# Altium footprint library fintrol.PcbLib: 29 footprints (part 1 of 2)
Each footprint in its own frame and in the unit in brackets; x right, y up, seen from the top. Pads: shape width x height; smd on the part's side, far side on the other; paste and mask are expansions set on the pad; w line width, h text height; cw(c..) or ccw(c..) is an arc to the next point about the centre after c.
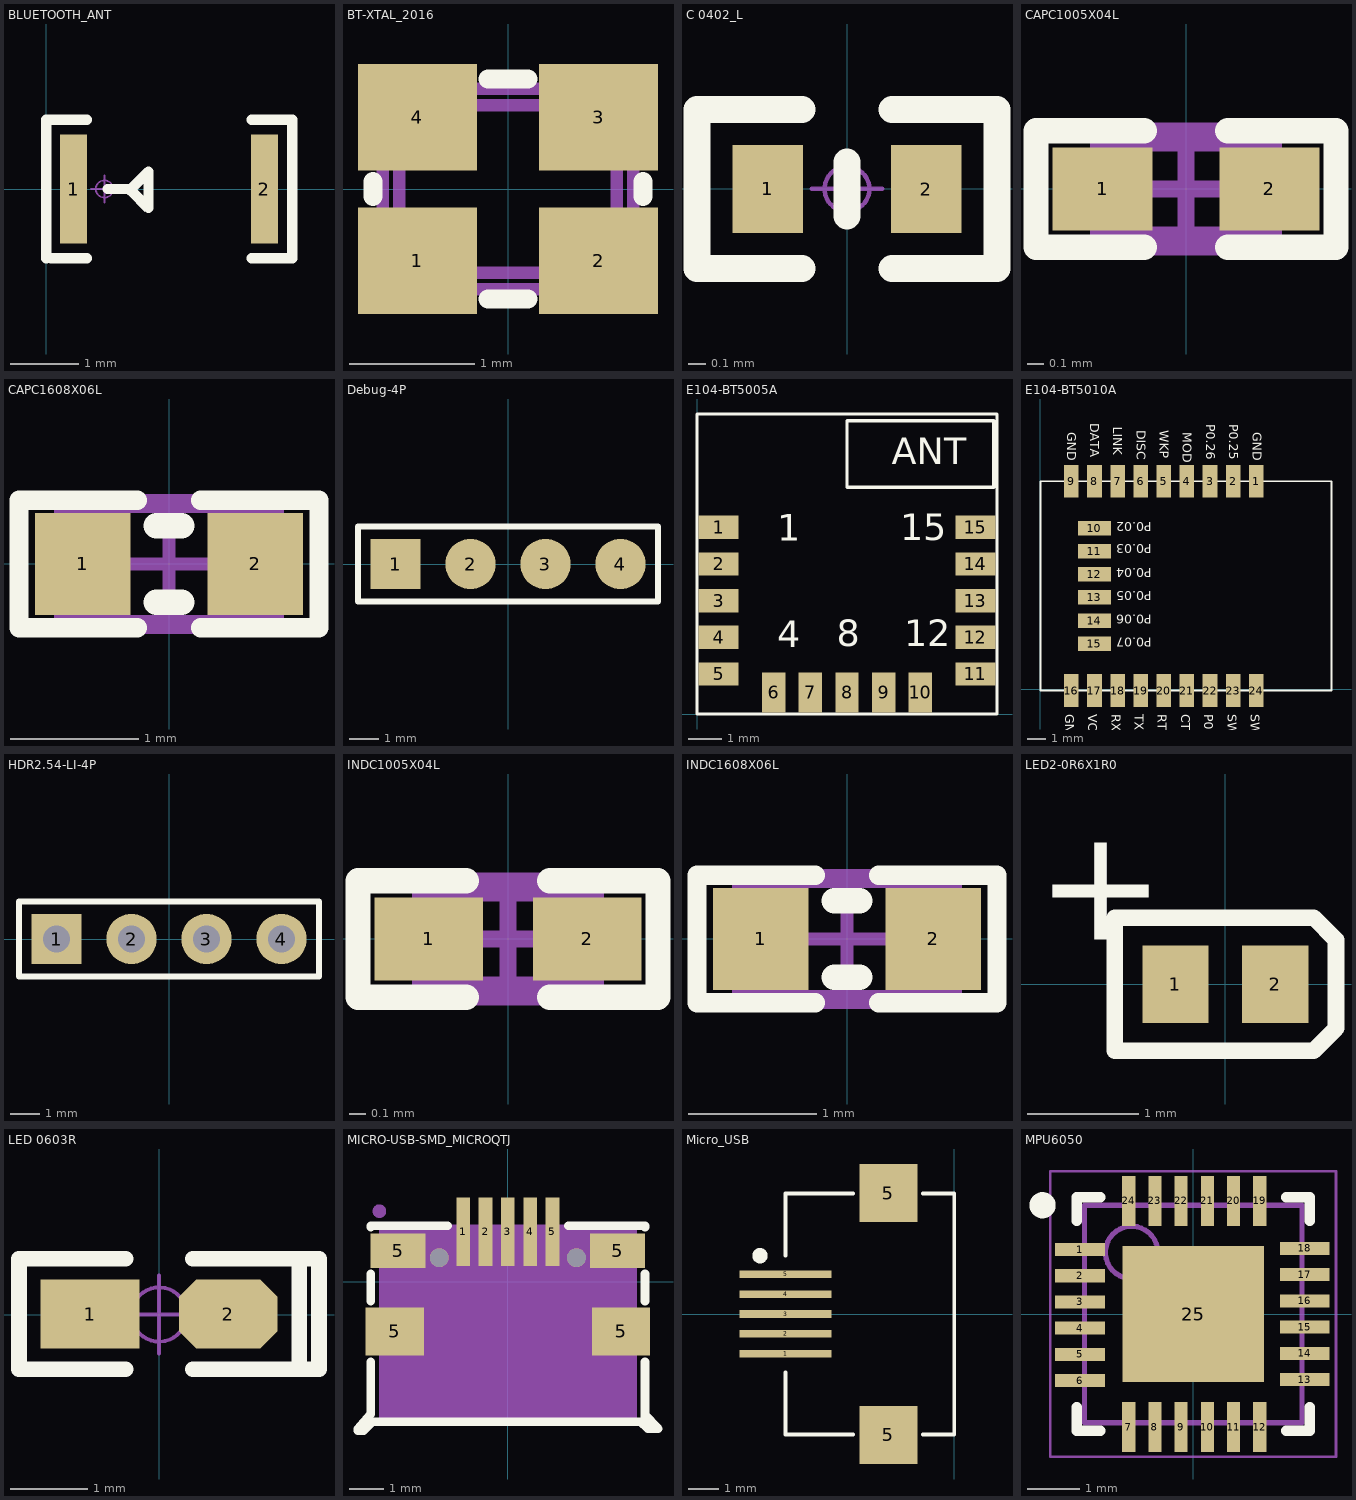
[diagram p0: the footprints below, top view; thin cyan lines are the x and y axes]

## BLUETOOTH_ANT [mm] "陶瓷表贴蓝牙天线"
pads (2):
  rect 0.4x1.6 smd: 1(0.4,0) 2(3.2,0)
Top Overlay:
  lines w0.152: 0,-1.016 0,-0.889 0,-0.62 0,1.016 0.596,1.016 ; 0.071,-1.016 0.596,-1.016 ; 0.901,0 1.228,0 1.228,-0.017 1.499,0.254 1.499,-0.279 1.245,-0.025 ; 3.011,-1.016 3.607,-1.016 3.607,1.016 3.011,1.016
Mechanical 15:
  circle w0.025: c0.853,0 r0.127
  lines w0.025: 0.653,0 1.052,0 ; 0.853,-0.2 0.853,0.2

## BT-XTAL_2016 [mm]
pads (4):
  rect 0.95x0.85 smd: 1(-0.725,-0.575) 2(0.725,-0.575) 3(0.725,0.575) 4(-0.725,0.575)
Top Overlay:
  lines w0.152: -1.08,-0.06 -1.08,0.06 ; -0.16,-0.88 0.16,-0.88 ; -0.16,0.88 0.16,0.88 ; 1.08,-0.06 1.08,0.06
Mechanical 7:
  lines w0.1: -1,-0.7 cw(c-1,-0.8) -0.9,-0.8 0.9,-0.8 cw(c1,-0.8) 1,-0.7 1,0.7 cw(c1,0.8) 0.9,0.8 -0.9,0.8 cw(c-1,0.8) -1,0.7 -1,-0.7 ; -0.87,-0.57 ccw(c-0.77,-0.57) -0.77,-0.67 0.77,-0.67 ccw(c0.77,-0.57) 0.87,-0.57 0.87,0.57 ccw(c0.77,0.57) 0.77,0.67 -0.77,0.67 ccw(c-0.77,0.57) -0.87,0.57 -0.87,-0.57
  text ".Designator" at -0.7,-0.2 h0.38
3D body "User Library-GeyerElectronics_KX5.step": height 0.56, standoff 0, extent -1.05,-0.85 1.05,0.85
3D body: height 0.56, standoff 0.15, extent -0.7,-0.65 0.7,0.65

## C 0402_L [mm] "无极性贴片电容"
pads (2):
  rect 0.4x0.5 smd: 1(-0.45,0) 2(0.45,0)
Top Overlay:
  lines w0.152: -0.254,-0.45 -0.85,-0.45 ; -0.254,0.45 -0.85,0.45 -0.85,-0.45 ; 0,-0.152 0,0.152 ; 0.254,-0.45 0.85,-0.45 0.85,0.45 0.254,0.45 ; -0.85,-0.45 -0.85,-0.45
Mechanical 15:
  circle w0.025: c0,0 r0.127
  lines w0.025: -0.2,0 0.2,0 ; 0,-0.2 0,0.2
3D body "C 0402.STEP": height 0.53, standoff 0.01, extent -0.5,-0.26 0.5,0.26

## CAPC1005X04L [mm]
pads (2):
  rect 0.6x0.5 smd: 1(-0.5,0) 2(0.5,0)
Top Overlay:
  lines w0.152: -0.25,-0.35 -0.9,-0.35 -0.9,0.35 -0.25,0.35 ; 0.25,-0.35 0.9,-0.35 0.9,0.35 0.25,0.35
Mechanical 7:
  lines w0.1: -0.525,-0.275 -0.525,0.275 0.525,0.275 0.525,-0.275 -0.525,-0.275
  text ".Designator" at -0.432,-0.152 h0.3
Mechanical 15:
  lines w0.1: -0.275,0 0.275,0 ; 0,-0.275 0,0.275 ; -0.9,-0.35 0.9,-0.35 0.9,0.35 -0.9,0.35 -0.9,-0.35
3D body "User Library-0402(1005M) Cap.step": height 0.5, standoff -0.01, extent -0.508,-0.254 0.508,0.254

## CAPC1608X06L [mm]
pads (2):
  rect 0.75x0.8 smd: 1(-0.675,0) 2(0.675,0)
Top Overlay:
  lines w0.152: -0.25,-0.5 -1.175,-0.5 -1.175,0.5 -0.25,0.5 ; 0.25,-0.5 1.175,-0.5 1.175,0.5 0.25,0.5
  lines w0.2: -0.1,-0.3 0.1,-0.3 ; -0.1,0.3 0.1,0.3
Mechanical 7:
  lines w0.1: -0.85,-0.45 0.85,-0.45 0.85,0.45 -0.85,0.45 -0.85,-0.45
  text ".Designator" at -0.685,-0.142 h0.38
Mechanical 15:
  lines w0.1: -0.45,0 0.45,0 ; 0,-0.45 0,0.45 ; -1.175,-0.5 -1.175,0.5 1.175,0.5 1.175,-0.5 -1.175,-0.5
3D body "User Library-Chip Capacitor 0603.step": height 0.8, standoff 0, extent -0.8,-0.43 0.8,0.43

## Debug-4P [mm]
pads (4):
  rect 1.7x1.7 smd: 1(-3.81,0)
  round 1.7 smd: 2(-1.27,0) 3(1.27,0) 4(3.81,0)
Top Overlay:
  lines w0.2: -5.08,-1.27 -5.08,1.27 5.08,1.27 5.08,-1.27 -5.08,-1.27

## E104-BT5005A [mm]
pads (15):
  rect 1.2x0.7 smd: 1(0.65,5.6) 2(0.65,4.5) 3(0.65,3.4) 4(0.65,2.3) 5(0.65,1.2) 11(8.35,1.2) 12(8.35,2.3) 13(8.35,3.4) 14(8.35,4.5) 15(8.35,5.6)
  rect 0.7x1.2 smd: 6(2.3,0.65) 7(3.4,0.65) 8(4.5,0.65) 9(5.6,0.65) 10(6.7,0.65)
Top Overlay:
  lines w0.1: 0,0 0,0.5 0,9 9,9 9,0 8.5,0 0,0 ; 4.5,6.8 8.9,6.8 8.9,8.8 4.5,8.8 4.5,6.8
  text "ANT" at 5.842,7.493 h0.8
  text "15" at 6.096,5.207 h0.8
  text "12" at 6.223,2.032 h0.8
  text "8" at 4.191,2.032 h0.8
  text "4" at 2.4,2 h0.8
  text "1" at 2.4,5.2 h0.8

## E104-BT5010A [mm]
pads (24):
  rect 0.8x1.8 smd: 1(11.86,11.43) 2(10.59,11.43) 3(9.32,11.43) 4(8.05,11.43) 5(6.78,11.43) 6(5.51,11.43) 7(4.24,11.43) 8(2.97,11.43) 9(1.7,11.43) 16(1.7,-0.07) 17(2.97,-0.07) 18(4.24,-0.07) 19(5.51,-0.07) 20(6.78,-0.07) 21(8.05,-0.07) 22(9.32,-0.07) 23(10.59,-0.07) 24(11.86,-0.07)
  rect 1.8x0.8 smd: 10(2.97,8.855) 11(2.97,7.585) 12(2.97,6.315) 13(2.97,5.045) 14(2.97,3.775) 15(2.97,2.505)
Top Overlay:
  lines w0.1: 0,-0.07 0,11.43 16,11.43 16,-0.07 0,-0.07
  text "GND" at 1.36,-1.361 h0.5
  text "GND" at 1.46,14.139 h0.5
  text "P0.03" at 6.123,7.976 h0.5
  text "P0.06" at 6.123,4.105 h0.5
  text "P0.02" at 6.123,9.174 h0.5
  text "P0.04" at 6.123,6.645 h0.5
  text "P0.05" at 6.123,5.375 h0.5
  text "P0.07" at 6.123,2.835 h0.5
  text "SWDIO" at 11.56,-1.361 h0.5
  text "SWDCLK" at 10.285,-1.361 h0.5
  text "P0.21/RST" at 9.01,-1.361 h0.5
  text "CTS" at 7.735,-1.361 h0.5
  text "RTS" at 6.46,-1.361 h0.5
  text "TXD" at 5.185,-1.361 h0.5
  text "RXD" at 3.91,-1.361 h0.5
  text "VCC" at 2.635,-1.361 h0.5
  text "DATA" at 2.735,14.63 h0.5
  text "LINK" at 4.01,14.427 h0.5
  text "DISC" at 5.285,14.236 h0.5
  text "WKP" at 6.56,14.242 h0.5
  text "MOD" at 7.835,14.139 h0.5
  text "P0.26" at 9.11,14.567 h0.5
  text "P0.25" at 10.385,14.567 h0.5
  text "GND" at 11.66,14.139 h0.5

## HDR2.54-LI-4P [mm] "排针，4脚"
pads (4):
  rect 1.7x1.7 hole 0.9: 1(-3.81,0)
  round 1.7 hole 0.9: 2(-1.27,0) 3(1.27,0) 4(3.81,0)
Top Overlay:
  lines w0.2: -5.08,-1.27 -5.08,1.27 5.08,1.27 5.08,-1.27 -5.08,-1.27
3D body "HDR2.54-1P.STEP": height 8.5, standoff -3, extent -5.08,-1.27 -2.54,1.27
3D body "HDR2.54-1P.STEP": height 8.5, standoff -3, extent -2.54,-1.27 0,1.27
3D body "HDR2.54-1P.STEP": height 8.5, standoff -3, extent 0,-1.27 2.54,1.27
3D body "HDR2.54-1P.STEP": height 8.5, standoff -3, extent 2.54,-1.27 5.08,1.27

## INDC1005X04L [mm]
pads (2):
  rect 0.65x0.5 smd: 1(-0.475,0) 2(0.475,0)
Top Overlay:
  lines w0.152: -0.25,-0.35 -0.9,-0.35 -0.9,0.35 -0.25,0.35 ; 0.25,-0.35 0.9,-0.35 0.9,0.35 0.25,0.35
Mechanical 7:
  lines w0.1: -0.525,-0.275 0.525,-0.275 0.525,0.275 -0.525,0.275 -0.525,-0.275
  text ".Designator" at -0.432,-0.152 h0.3
Mechanical 15:
  lines w0.1: -0.275,0 0.275,0 ; 0,-0.275 0,0.275 ; -0.9,-0.35 0.9,-0.35 0.9,0.35 -0.9,0.35 -0.9,-0.35
3D body "User Library-Chip Inductor 0402.step": height 0.5, standoff 0, extent -0.5,-0.3 0.5,0.3

## INDC1608X06L [mm]
pads (2):
  rect 0.75x0.8 smd: 1(-0.675,0) 2(0.675,0)
Top Overlay:
  lines w0.152: -0.25,-0.5 -1.175,-0.5 -1.175,0.5 -0.25,0.5 ; 0.25,-0.5 1.175,-0.5 1.175,0.5 0.25,0.5
  lines w0.2: -0.1,-0.3 0.1,-0.3 ; -0.1,0.3 0.1,0.3
Mechanical 7:
  lines w0.1: -0.85,-0.45 0.85,-0.45 0.85,0.45 -0.85,0.45 -0.85,-0.45
  text ".Designator" at -0.7,-0.2 h0.38
Mechanical 15:
  lines w0.1: -0.45,0 0.45,0 ; 0,-0.45 0,0.45 ; -1.175,-0.5 -1.175,0.5 1.175,0.5 1.175,-0.5 -1.175,-0.5
3D body "User Library-Chip Inductor.step": height 0.8, standoff 0, extent -0.8,-0.475 0.8,0.475

## LED2-0R6X1R0 [mm]
pads (2):
  rect 0.6x0.7 smd: 1(-0.45,0) 2(0.45,0)
Top Overlay:
  lines w0.15: -1,-0.6 -1,0.6 0.8,0.6 1,0.4 1,-0.4 0.8,-0.6 -1,-0.6
  text "+" at -1.71,0.4 h1.02

## LED 0603R [mil] "红色0603LED"
pads (2):
  rect 50x35 smd: 1(-35,0.26)
  oct 50x35 smd: 2(35,0.26)
Top Overlay:
  lines w8: -17,-27.74 -71,-27.74 -71,-25.74 -71,28.26 -70,28.26 -17,28.26 ; 17,-27.74 70,-27.74 ; 17,28.26 71,28.26 81,28.26 81,-27.74 71,-27.74 71,26.26
Mechanical 15:
  circle w1.97: c0,0 r13.78
  lines w1.97: -19.68,0 19.68,0 ; 0,-19.68 0,19.68
3D body "LED 0603玻璃罩.": height 0, standoff 0, extent 0,0 0,0
3D body "LED 0603-R.STEP": height 18.36, standoff -0.16, extent -31.5,-15.79 31.5,15.79

## MICRO-USB-SMD_MICROQTJ [mm]
pads (11):
  rect 0.4x2 smd: 1(-1.3,1.452) 2(-0.65,1.452) 3(0,1.452) 4(0.65,1.452) 5(1.3,1.452)
  rect 1.7x1.4 smd: 5(-3.3,-1.452) 5(3.3,-1.452)
  rect 1.6x1 smd: 5(-3.2,0.902) 5(3.2,0.902)
  round 0.55 hole 0.55 unplated: ""(-2,0.698) ""(2,0.698)
Top Overlay:
  lines w0.254: -4.011,-3.869 -4.369,-4.288 -4.369,-4.339 -4.204,-4.339 -3.946,-4.081 3.878,-4.081 4.084,-4.288 4.376,-4.288 3.99,-3.869 ; -4,-3.869 -4,-2.398 -4,-2.334 ; -4,-0.571 -4,0.22 ; -4,1.583 -4,1.633 -1.758,1.633 ; 1.758,1.633 4,1.633 4,1.583 ; 4,-3.991 4,-2.398 4,-2.334 ; 4,-0.571 4,0.22
Mechanical 4:
  circle w0.275: c2,0.698 r0.137
  circle w0.275: c-2,0.698 r0.137
  region: 3.754,-4.143 -3.746,-4.143 -3.746,1.657 3.754,1.657
Mechanical 5:
  region: 1.175,0.952 1.175,2.052 1.425,2.052 1.425,0.952
  region: 0.525,0.952 0.525,2.052 0.775,2.052 0.775,0.952
  region: -0.125,0.952 -0.125,2.052 0.125,2.052 0.125,0.952
  region: -0.775,0.952 -0.775,2.052 -0.525,2.052 -0.525,0.952
  region: -1.425,0.952 -1.425,2.052 -1.175,2.052 -1.175,0.952
  region: 2.525,-0.902 4.075,-0.902 4.075,-2.002 2.525,-2.002
  region: -4.075,-0.902 -2.525,-0.902 -2.525,-2.002 -4.075,-2.002
  region: 2.55,1.252 3.85,1.252 3.85,0.552 2.55,0.552
  region: -3.85,1.252 -2.55,1.252 -2.55,0.552 -3.85,0.552
Mechanical 6:
  circle w0.2: c-3.746,2.053 r0.1

## Micro_USB [mm] "5P 贴片 带定位柱"
pads (7):
  rect 3x0.25 smd: 1(-5.508,-1.3) 2(-5.508,-0.65) 3(-5.508,0) 4(-5.508,0.65) 5(-5.508,1.3)
  rect 1.9x1.9 smd: 5(-2.15,-3.95) 5(-2.15,3.95)
Top Overlay:
  circle w0.25: c-6.348,1.905 r0.125
  lines w0.127: -5.508,-3.937 -3.302,-3.937 ; -5.508,-3.9 -5.508,-1.905 ; -5.508,1.905 -5.508,3.9 ; -5.508,3.937 -3.302,3.937 ; -1.016,-3.937 0,-3.937 ; -1.016,3.937 0,3.937 ; 0,-3.9 0,3.9

## MPU6050 [mm] "QFN, 24-Leads, Body 4.00x4.00mm, Pitch 0.50mm, Thermal Pad 2.70x2.60mm, IPC Medium Density"
height 0.9
pads (25):
  rect 0.95x0.25 smd: 1(-2.159,1.23) 2(-2.159,0.73) 3(-2.159,0.23) 4(-2.159,-0.27) 5(-2.159,-0.77) 6(-2.159,-1.27) 13(2.127,-1.25) 14(2.127,-0.75) 15(2.127,-0.25) 16(2.127,0.25) 17(2.127,0.75) 18(2.127,1.25)
  rect 0.25x0.95 smd: 7(-1.23,-2.159) 8(-0.73,-2.159) 9(-0.23,-2.159) 10(0.27,-2.159) 11(0.77,-2.159) 12(1.27,-2.159) 19(1.27,2.159) 20(0.77,2.159) 21(0.27,2.159) 22(-0.23,2.159) 23(-0.73,2.159) 24(-1.23,2.159)
  rect 2.7x2.6 smd: 25(0,0)
Top Overlay:
  circle w0.25: c-2.875,2.075 r0.125
  lines w0.2: -2.225,-1.775 -2.225,-2.225 -1.775,-2.225 ; -2.225,1.775 -2.225,2.225 -1.775,2.225 ; 1.775,-2.225 2.225,-2.225 2.225,-1.775 ; 1.775,2.225 2.225,2.225 2.225,1.775
Mechanical 13:
  circle w0.1: c-1.175,1.175 r0.5
  lines w0.1: -2.075,-2.075 2.075,-2.075 2.075,2.075 -2.075,2.075 -2.075,-2.075
Mechanical 15:
  lines w0.05: -2.725,-2.725 2.725,-2.725 2.725,2.725 -2.725,2.725 -2.725,-2.725
  lines w0.1: -0.5,0 0.5,0 ; 0,-0.5 0,0.5
3D body: height 0.9, standoff 0.01, extent -2.075,-2.075 2.075,2.075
